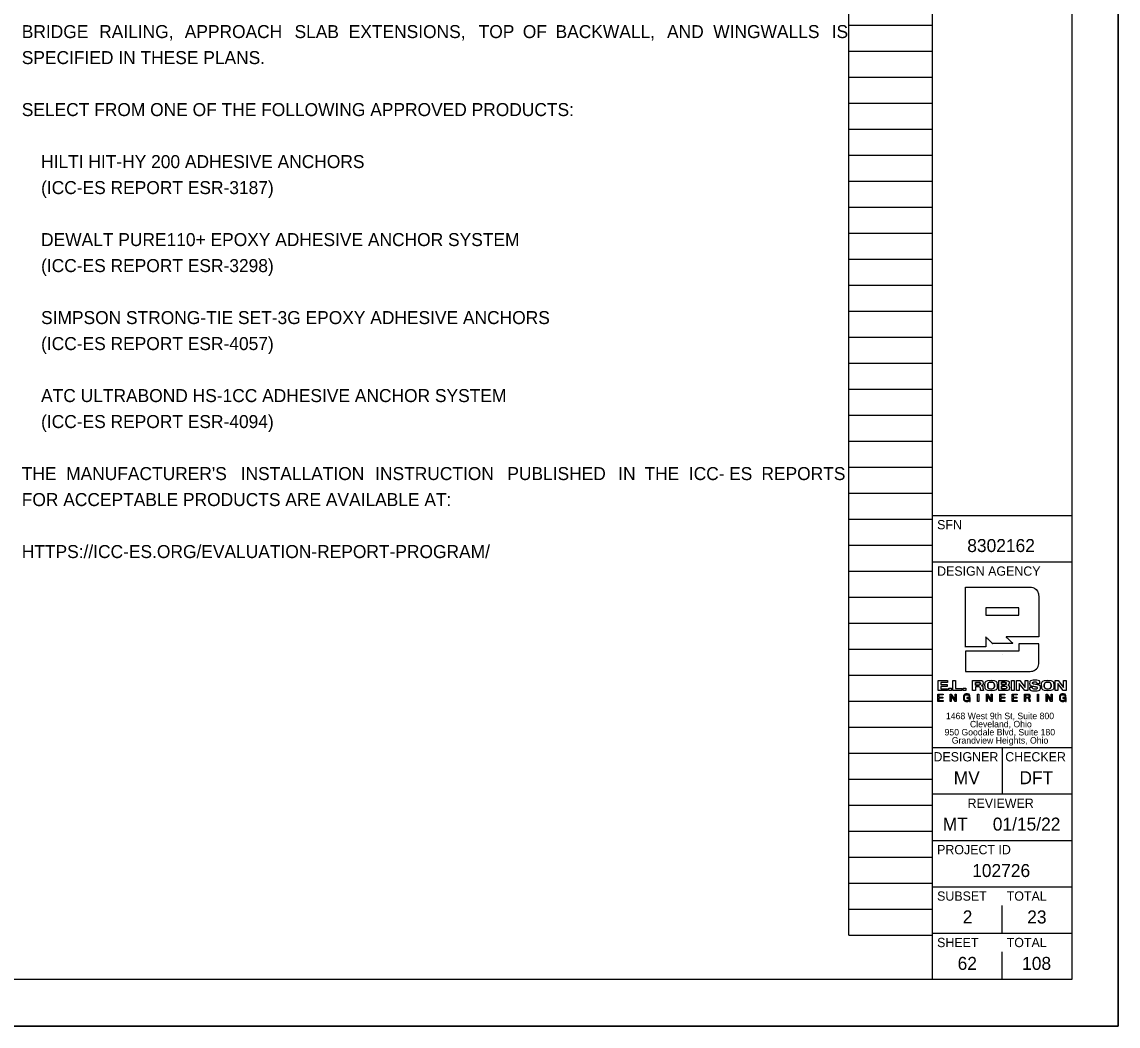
# Model space of a CAD drawing. Extents: x 0 to 34, y 0 to 22.
# Drawn here: x 22.19 to 34, y 0 to 10.81 of the extents above; entities that cross this region are included whole.
import ezdxf

# ---------------------------------------------------------------- set-up
doc = ezdxf.new("R2010")
doc.units = 0
for name, color, linetype in [('SC_Scratch1', 7, 'Continuous'), ('SH_Border', 7, 'Continuous'), ('SH_Cut_Line', 7, 'Continuous'), ('SH_Data', 7, 'Continuous'), ('SH_Text', 7, 'Continuous')]:
    doc.layers.add(name, color=color, linetype=linetype)

msp = doc.modelspace()

# ---------------------------------------------------------------- linework, layer by layer
at = {"layer": 'SC_Scratch1'}
for p, q in [((31.1, 0.98), (31.1, 21.14)), ((32, 0.98), (32, 21.14)), ((31.1, 10.78), (32, 10.78)), ((31.1, 10.5), (32, 10.5)), ((31.1, 10.22), (32, 10.22)), ((31.1, 9.94), (32, 9.94)), ((31.1, 9.66), (32, 9.66)), ((31.1, 9.38), (32, 9.38)), ((31.1, 9.1), (32, 9.1)), ((31.1, 8.82), (32, 8.82)), ((31.1, 8.54), (32, 8.54)), ((31.1, 8.26), (32, 8.26)), ((31.1, 7.98), (32, 7.98)), ((31.1, 7.7), (32, 7.7)), ((31.1, 7.42), (32, 7.42)), ((31.1, 7.14), (32, 7.14)), ((31.1, 6.86), (32, 6.86)), ((31.1, 6.58), (32, 6.58)), ((31.1, 6.3), (32, 6.3)), ((31.1, 6.02), (32, 6.02)), ((31.1, 5.74), (32, 5.74)), ((31.1, 5.46), (32, 5.46)), ((31.1, 5.18), (32, 5.18)), ((31.1, 4.9), (32, 4.9)), ((31.1, 4.62), (32, 4.62)), ((31.1, 4.34), (32, 4.34)), ((31.1, 4.06), (32, 4.06)), ((31.1, 3.78), (32, 3.78)), ((31.1, 3.5), (32, 3.5)), ((31.1, 3.22), (32, 3.22)), ((31.1, 2.94), (32, 2.94)), ((31.1, 2.66), (32, 2.66)), ((31.1, 2.38), (32, 2.38)), ((31.1, 2.1), (32, 2.1)), ((31.1, 1.82), (32, 1.82)), ((31.1, 1.54), (32, 1.54)), ((31.1, 1.26), (32, 1.26)), ((31.1, 0.98), (32, 0.98))]:
    msp.add_line(p, q, dxfattribs=at)
msp.add_lwpolyline([(0, 22), (34, 22), (34, 0), (0, 0)], close=True, dxfattribs=at)
at = {"layer": 'SH_Border'}
for p, q in [((32, 0.5), (32, 21.5)), ((32, 5.5), (33.5, 5.5)), ((32, 5), (33.5, 5)), ((32, 3), (33.5, 3)), ((32.75, 3), (32.75, 2.5)), ((32, 2.5), (33.5, 2.5)), ((32, 2), (33.5, 2)), ((32, 1.5), (33.5, 1.5)), ((32, 1), (33.5, 1))]:
    msp.add_line(p, q, dxfattribs=at)
msp.add_lwpolyline([(1.5, 21.5), (33.5, 21.5), (33.5, 0.5), (1.5, 0.5)], close=True, dxfattribs=at)
at = {"layer": 'SH_Cut_Line'}
msp.add_lwpolyline([(0, 0), (34, 0), (34, 22), (0, 22)], close=True, dxfattribs=at)
at = {"layer": 'SH_Data'}
for p, q in [((32.929, 4.503), (32.574, 4.503)), ((32.574, 4.503), (32.574, 4.425)), ((32.929, 4.425), (32.929, 4.503)), ((32.574, 4.425), (32.929, 4.425)), ((32.75, 4), (32.75, 4)), ((32.463, 3.701), (32.463, 3.673)), ((32.743, 3.702), (32.743, 3.678)), ((32.743, 3.659), (32.743, 3.633)), ((33.001, 3.566), (33.001, 3.539)), ((33.001, 3.539), (33.023, 3.539)), ((32.75, 1), (32.75, 1.3)), ((32.75, 0.5), (32.75, 0.8)), ((32.375, 0.675), (32.375, 0.675))]:
    msp.add_line(p, q, dxfattribs=at)
for points in [[(32.06, 3.721), (32.161, 3.721), (32.161, 3.701), (32.089, 3.701), (32.089, 3.678), (32.158, 3.678), (32.158, 3.658), (32.089, 3.658), (32.089, 3.633), (32.162, 3.633), (32.162, 3.613), (32.06, 3.613), (32.06, 3.721)], [(32.22, 3.721), (32.249, 3.721), (32.249, 3.634), (32.316, 3.634), (32.316, 3.613), (32.22, 3.613), (32.22, 3.721)], [(32.851, 3.721), (32.881, 3.721), (32.881, 3.613), (32.851, 3.613), (32.851, 3.721)], [(32.999, 3.721), (33.027, 3.721), (33.027, 3.613), (32.995, 3.613), (32.936, 3.689), (32.936, 3.689), (32.936, 3.613), (32.907, 3.613), (32.907, 3.721), (32.941, 3.721), (32.999, 3.646), (32.999, 3.646), (32.999, 3.721)], [(33.413, 3.721), (33.442, 3.721), (33.442, 3.613), (33.41, 3.613), (33.35, 3.689), (33.35, 3.689), (33.35, 3.613), (33.321, 3.613), (33.321, 3.721), (33.356, 3.721), (33.413, 3.646), (33.413, 3.646), (33.413, 3.721)], [(32.059, 3.575), (32.114, 3.575), (32.114, 3.566), (32.07, 3.566), (32.07, 3.541), (32.111, 3.541), (32.111, 3.532), (32.07, 3.532), (32.07, 3.505), (32.114, 3.505), (32.114, 3.496), (32.059, 3.496), (32.059, 3.575)], [(32.175, 3.639), (32.205, 3.639), (32.205, 3.613), (32.175, 3.613), (32.175, 3.639)], [(32.191, 3.575), (32.203, 3.575), (32.244, 3.511), (32.244, 3.511), (32.244, 3.575), (32.254, 3.575), (32.254, 3.496), (32.243, 3.496), (32.202, 3.559), (32.201, 3.559), (32.201, 3.496), (32.191, 3.496), (32.191, 3.575)], [(32.331, 3.639), (32.361, 3.639), (32.361, 3.613), (32.331, 3.613), (32.331, 3.639)], [(32.487, 3.575), (32.498, 3.575), (32.498, 3.496), (32.487, 3.496), (32.487, 3.575)], [(32.581, 3.575), (32.592, 3.575), (32.633, 3.511), (32.633, 3.511), (32.633, 3.575), (32.643, 3.575), (32.643, 3.496), (32.632, 3.496), (32.591, 3.559), (32.591, 3.559), (32.591, 3.496), (32.581, 3.496), (32.581, 3.575)], [(32.726, 3.575), (32.781, 3.575), (32.781, 3.566), (32.737, 3.566), (32.737, 3.541), (32.778, 3.541), (32.778, 3.532), (32.737, 3.532), (32.737, 3.505), (32.781, 3.505), (32.781, 3.496), (32.726, 3.496), (32.726, 3.575)], [(32.859, 3.575), (32.913, 3.575), (32.913, 3.566), (32.869, 3.566), (32.869, 3.541), (32.91, 3.541), (32.91, 3.532), (32.869, 3.532), (32.869, 3.505), (32.913, 3.505), (32.913, 3.496), (32.859, 3.496), (32.859, 3.575)], [(33.133, 3.575), (33.143, 3.575), (33.143, 3.496), (33.133, 3.496), (33.133, 3.575)], [(33.226, 3.575), (33.237, 3.575), (33.279, 3.511), (33.279, 3.511), (33.279, 3.575), (33.289, 3.575), (33.289, 3.496), (33.277, 3.496), (33.236, 3.559), (33.236, 3.559), (33.236, 3.496), (33.226, 3.496), (33.226, 3.575)]]:
    msp.add_lwpolyline(points, dxfattribs=at)
for points, degree in [([(32.356, 4.083), (32.356, 4.086), (32.356, 4.724), (32.356, 4.727)], 2), ([(32.356, 4.727), (32.36, 4.727), (33.03, 4.727), (33.034, 4.727), (33.096, 4.727), (33.147, 4.677), (33.147, 4.614)], 3), ([(33.147, 4.614), (33.147, 4.612), (33.147, 4.194), (33.147, 4.192)], 2), ([(32.645, 4.121), (32.645, 4.121), (32.574, 4.191), (32.574, 4.192)], 2), ([(32.574, 4.192), (32.574, 4.191), (32.574, 4.083), (32.574, 4.083)], 2), ([(33.147, 4.192), (33.145, 4.192), (32.795, 4.192), (32.793, 4.192)], 2), ([(32.793, 4.192), (32.793, 4.191), (32.866, 4.121), (32.866, 4.121)], 2), ([(32.929, 4.115), (32.929, 4.115), (33.147, 4.115), (33.147, 4.115), (33.147, 4.115), (33.147, 3.933), (33.147, 3.933), (33.147, 3.87), (33.096, 3.82), (33.034, 3.82), (33.034, 3.82), (32.356, 3.82), (32.356, 3.82), (32.356, 3.82), (32.356, 4.037), (32.356, 4.037), (32.356, 4.037), (32.929, 4.037), (32.929, 4.037), (32.929, 4.037), (32.929, 4.115), (32.929, 4.115)], 3), ([(32.574, 4.083), (32.573, 4.083), (32.357, 4.083), (32.356, 4.083)], 2), ([(32.866, 4.121), (32.865, 4.121), (32.646, 4.121), (32.645, 4.121)], 2), ([(32.433, 3.613), (32.433, 3.613), (32.433, 3.721), (32.433, 3.721)], 2), ([(32.433, 3.721), (32.433, 3.721), (32.512, 3.721), (32.512, 3.721), (32.542, 3.721), (32.545, 3.703), (32.546, 3.692)], 3), ([(32.463, 3.673), (32.463, 3.673), (32.502, 3.673), (32.502, 3.673), (32.508, 3.673), (32.516, 3.677), (32.516, 3.687), (32.516, 3.698), (32.507, 3.701), (32.5, 3.701), (32.5, 3.701), (32.463, 3.701), (32.463, 3.701), (32.463, 3.701), (32.463, 3.673), (32.463, 3.673)], 3), ([(32.463, 3.673), (32.476, 3.673), (32.489, 3.673), (32.508, 3.673), (32.516, 3.677), (32.516, 3.698), (32.507, 3.701), (32.488, 3.701), (32.475, 3.701), (32.463, 3.701)], 3), ([(32.546, 3.692), (32.544, 3.679), (32.542, 3.67), (32.53, 3.666)], 2), ([(32.53, 3.666), (32.53, 3.666), (32.53, 3.665), (32.53, 3.665)], 2), ([(32.53, 3.665), (32.543, 3.663), (32.544, 3.647), (32.544, 3.636)], 2), ([(32.631, 3.61), (32.573, 3.61), (32.567, 3.645), (32.565, 3.667), (32.564, 3.69), (32.573, 3.724), (32.631, 3.724)], 3), ([(32.631, 3.63), (32.658, 3.63), (32.667, 3.65), (32.667, 3.667), (32.667, 3.684), (32.658, 3.704), (32.631, 3.704), (32.604, 3.704), (32.595, 3.684), (32.595, 3.667), (32.595, 3.65), (32.604, 3.63), (32.631, 3.63)], 3), ([(32.631, 3.704), (32.604, 3.704), (32.595, 3.684), (32.595, 3.667), (32.595, 3.65), (32.604, 3.63), (32.631, 3.63)], 3), ([(32.631, 3.724), (32.69, 3.724), (32.695, 3.689), (32.697, 3.667), (32.699, 3.644), (32.69, 3.61), (32.631, 3.61)], 3), ([(32.631, 3.63), (32.658, 3.63), (32.667, 3.65), (32.667, 3.667), (32.667, 3.684), (32.658, 3.704), (32.631, 3.704)], 3), ([(32.714, 3.613), (32.714, 3.613), (32.714, 3.721), (32.714, 3.721)], 2), ([(32.714, 3.721), (32.714, 3.721), (32.795, 3.721), (32.795, 3.721)], 2), ([(32.743, 3.678), (32.743, 3.678), (32.784, 3.678), (32.784, 3.678), (32.791, 3.678), (32.796, 3.682), (32.796, 3.69), (32.796, 3.697), (32.793, 3.702), (32.78, 3.702), (32.78, 3.702), (32.743, 3.702), (32.743, 3.702), (32.743, 3.702), (32.743, 3.678), (32.743, 3.678)], 3), ([(32.743, 3.678), (32.757, 3.678), (32.771, 3.678), (32.791, 3.681), (32.791, 3.683), (32.792, 3.697), (32.793, 3.702), (32.768, 3.702), (32.756, 3.702), (32.743, 3.702)], 3), ([(32.795, 3.721), (32.81, 3.718), (32.826, 3.714), (32.826, 3.694)], 2), ([(32.826, 3.694), (32.824, 3.686), (32.822, 3.675), (32.812, 3.672)], 2), ([(32.812, 3.672), (32.812, 3.672), (32.812, 3.672), (32.812, 3.672)], 2), ([(32.812, 3.672), (32.824, 3.67), (32.827, 3.656), (32.829, 3.645)], 2), ([(33.126, 3.69), (33.124, 3.704), (33.111, 3.706), (33.099, 3.706), (33.087, 3.706), (33.079, 3.7), (33.079, 3.693), (33.079, 3.687), (33.084, 3.684), (33.091, 3.683), (33.091, 3.683), (33.128, 3.677), (33.128, 3.677), (33.148, 3.673), (33.163, 3.666), (33.163, 3.646), (33.163, 3.626), (33.149, 3.61), (33.107, 3.61), (33.08, 3.61), (33.046, 3.613), (33.045, 3.647), (33.045, 3.647), (33.079, 3.647), (33.079, 3.647), (33.079, 3.632), (33.094, 3.629), (33.107, 3.629), (33.121, 3.629), (33.13, 3.634), (33.13, 3.643), (33.13, 3.651), (33.123, 3.654), (33.112, 3.655), (33.112, 3.655), (33.085, 3.66), (33.085, 3.66), (33.066, 3.662), (33.047, 3.668), (33.047, 3.69), (33.047, 3.715), (33.067, 3.724), (33.101, 3.724), (33.124, 3.724), (33.157, 3.721), (33.159, 3.69), (33.159, 3.69), (33.126, 3.69), (33.126, 3.69)], 3), ([(33.242, 3.61), (33.183, 3.61), (33.178, 3.645), (33.176, 3.667), (33.174, 3.69), (33.183, 3.724), (33.242, 3.724)], 3), ([(33.242, 3.63), (33.269, 3.63), (33.278, 3.65), (33.278, 3.667), (33.278, 3.684), (33.269, 3.704), (33.242, 3.704), (33.215, 3.704), (33.205, 3.684), (33.205, 3.667), (33.205, 3.65), (33.215, 3.63), (33.242, 3.63)], 3), ([(33.242, 3.704), (33.215, 3.704), (33.205, 3.684), (33.205, 3.667), (33.205, 3.65), (33.215, 3.63), (33.242, 3.63)], 3), ([(33.242, 3.724), (33.3, 3.724), (33.306, 3.689), (33.308, 3.667), (33.309, 3.644), (33.3, 3.61), (33.242, 3.61)], 3), ([(33.242, 3.63), (33.269, 3.63), (33.278, 3.65), (33.278, 3.667), (33.278, 3.684), (33.269, 3.704), (33.242, 3.704)], 3), ([(32.396, 3.506), (32.39, 3.498), (32.38, 3.494), (32.37, 3.494), (32.347, 3.494), (32.333, 3.514), (32.333, 3.534), (32.333, 3.557), (32.346, 3.577), (32.37, 3.577), (32.388, 3.577), (32.401, 3.569), (32.404, 3.551), (32.404, 3.551), (32.394, 3.551), (32.394, 3.551), (32.392, 3.562), (32.382, 3.568), (32.37, 3.568), (32.351, 3.568), (32.344, 3.551), (32.344, 3.534), (32.344, 3.518), (32.353, 3.503), (32.37, 3.503), (32.387, 3.503), (32.396, 3.515), (32.396, 3.529), (32.396, 3.529), (32.371, 3.529), (32.371, 3.529), (32.371, 3.529), (32.371, 3.538), (32.371, 3.538), (32.371, 3.538), (32.405, 3.538), (32.405, 3.538), (32.405, 3.538), (32.405, 3.496), (32.405, 3.496), (32.405, 3.496), (32.398, 3.496), (32.398, 3.496), (32.398, 3.496), (32.396, 3.506), (32.396, 3.506)], 3), ([(32.463, 3.613), (32.462, 3.613), (32.433, 3.613), (32.433, 3.613)], 2), ([(32.499, 3.653), (32.499, 3.653), (32.463, 3.653), (32.463, 3.653)], 2), ([(32.463, 3.653), (32.463, 3.652), (32.463, 3.613), (32.463, 3.613)], 2), ([(32.518, 3.613), (32.516, 3.618), (32.516, 3.622), (32.516, 3.634), (32.515, 3.649), (32.508, 3.65), (32.499, 3.653)], 3), ([(32.55, 3.613), (32.55, 3.613), (32.518, 3.613), (32.518, 3.613)], 2), ([(32.544, 3.636), (32.544, 3.631), (32.548, 3.619), (32.55, 3.613)], 2), ([(32.829, 3.645), (32.827, 3.632), (32.824, 3.613), (32.791, 3.613), (32.791, 3.613), (32.714, 3.613), (32.714, 3.613)], 3), ([(32.743, 3.633), (32.743, 3.633), (32.787, 3.633), (32.787, 3.633), (32.796, 3.633), (32.8, 3.639), (32.8, 3.646), (32.8, 3.655), (32.794, 3.659), (32.784, 3.659), (32.784, 3.659), (32.743, 3.659), (32.743, 3.659), (32.743, 3.659), (32.743, 3.633), (32.743, 3.633)], 3), ([(32.743, 3.633), (32.758, 3.633), (32.772, 3.633), (32.796, 3.633), (32.8, 3.639), (32.8, 3.655), (32.794, 3.659), (32.77, 3.659), (32.757, 3.659), (32.743, 3.659)], 3), ([(32.991, 3.575), (32.991, 3.575), (33.027, 3.575), (33.028, 3.575), (33.042, 3.575), (33.051, 3.567), (33.051, 3.554)], 3), ([(32.991, 3.496), (32.991, 3.497), (32.991, 3.574), (32.991, 3.575)], 2), ([(33.023, 3.539), (33.033, 3.539), (33.041, 3.541), (33.041, 3.552), (33.041, 3.56), (33.037, 3.566), (33.027, 3.566), (33.027, 3.566), (33.001, 3.566), (33.001, 3.566), (33.001, 3.566), (33.001, 3.539), (33.001, 3.539), (33.001, 3.539), (33.023, 3.539), (33.023, 3.539)], 3), ([(33.023, 3.539), (33.033, 3.539), (33.041, 3.541), (33.041, 3.56), (33.037, 3.566), (33.018, 3.566), (33.01, 3.566), (33.001, 3.566)], 3), ([(33.051, 3.554), (33.049, 3.545), (33.047, 3.537), (33.038, 3.534)], 2), ([(33.43, 3.506), (33.424, 3.498), (33.414, 3.494), (33.405, 3.494), (33.382, 3.494), (33.368, 3.514), (33.368, 3.534), (33.368, 3.557), (33.38, 3.577), (33.405, 3.577), (33.422, 3.577), (33.436, 3.569), (33.439, 3.551), (33.439, 3.551), (33.429, 3.551), (33.429, 3.551), (33.426, 3.562), (33.417, 3.568), (33.405, 3.568), (33.386, 3.568), (33.378, 3.551), (33.378, 3.534), (33.378, 3.518), (33.388, 3.503), (33.405, 3.503), (33.421, 3.503), (33.431, 3.515), (33.43, 3.529), (33.43, 3.529), (33.405, 3.529), (33.405, 3.529), (33.405, 3.529), (33.405, 3.538), (33.405, 3.538), (33.405, 3.538), (33.44, 3.538), (33.44, 3.538), (33.44, 3.538), (33.44, 3.496), (33.44, 3.496), (33.44, 3.496), (33.433, 3.496), (33.433, 3.496), (33.433, 3.496), (33.43, 3.506), (33.43, 3.506)], 3), ([(33.001, 3.496), (33.001, 3.496), (32.991, 3.496), (32.991, 3.496)], 2), ([(33.04, 3.516), (33.038, 3.523), (33.037, 3.53), (33.027, 3.53), (33.027, 3.53), (33.001, 3.53), (33.001, 3.53)], 3), ([(33.001, 3.53), (33.001, 3.53), (33.001, 3.496), (33.001, 3.496)], 2), ([(33.038, 3.534), (33.038, 3.534), (33.038, 3.534), (33.038, 3.534)], 2), ([(33.038, 3.534), (33.044, 3.529), (33.047, 3.525), (33.048, 3.518)], 2), ([(33.043, 3.496), (33.042, 3.5), (33.041, 3.508), (33.04, 3.516)], 2), ([(33.054, 3.496), (33.054, 3.496), (33.043, 3.496), (33.043, 3.496)], 2), ([(33.048, 3.518), (33.049, 3.51), (33.052, 3.502), (33.054, 3.496)], 2)]:
    msp.add_open_spline(points, degree=degree, dxfattribs=at)

# ---------------------------------------------------------------- texts
for s, height, p in [('SFN', 0.1, (32.05, 5.35)), ('8302162', 0.14, (32.375, 5.105)), ('DESIGN AGENCY', 0.1, (32.05, 4.85)), ('1468 West 9th St, Suite 800', 0.07, (32.145, 3.305)), ('950 Goodale Blvd, Suite 180', 0.07, (32.13, 3.13)), ('Cleveland, Ohio', 0.07, (32.404, 3.217)), ('Grandview Heights, Ohio', 0.07, (32.208, 3.042)), ('DESIGNER', 0.1, (32.011, 2.85)), ('CHECKER', 0.1, (32.784, 2.85)), ('MV', 0.14, (32.229, 2.605)), ('DFT', 0.14, (32.937, 2.605)), ('REVIEWER', 0.1, (32.378, 2.35)), ('MT', 0.14, (32.111, 2.105)), ('01/15/22', 0.14, (32.65, 2.105)), ('PROJECT ID', 0.1, (32.05, 1.85)), ('102726', 0.14, (32.428, 1.605)), ('SUBSET', 0.1, (32.05, 1.35)), ('TOTAL', 0.1, (32.8, 1.35)), ('2', 0.14, (32.326, 1.105)), ('23', 0.14, (33.021, 1.105)), ('SHEET', 0.1, (32.05, 0.85)), ('TOTAL', 0.1, (32.8, 0.85)), ('62', 0.14, (32.271, 0.605)), ('108', 0.14, (32.966, 0.605))]:
    msp.add_text(s, height=height, dxfattribs=at).set_placement(p)
at = {"layer": 'SH_Text'}
for s, p in [('BRIDGE ', (22.187, 10.64)), ('RAILING, ', (23.021, 10.64)), ('APPROACH ', (23.943, 10.64)), ('SLAB ', (25.126, 10.64)), ('EXTENSIONS, ', (25.71, 10.64)), ('TOP ', (27.11, 10.64)), ('OF ', (27.586, 10.64)), ('BACKWALL, ', (27.939, 10.64)), ('AND ', (29.14, 10.64)), ('WINGWALLS ', (29.638, 10.64)), ('IS ', (30.914, 10.64)), ('SPECIFIED IN THESE PLANS.', (22.187, 10.36)), ('SELECT FROM ONE OF THE FOLLOWING APPROVED PRODUCTS:   ', (22.187, 9.8)), ('    HILTI HIT-HY 200 ADHESIVE ANCHORS ', (22.187, 9.24)), ('    (ICC-ES REPORT ESR-3187) ', (22.187, 8.96)), ('    DEWALT PURE110+ EPOXY ADHESIVE ANCHOR SYSTEM  ', (22.187, 8.4)), ('    (ICC-ES REPORT ESR-3298) ', (22.187, 8.12)), ('    SIMPSON STRONG-TIE SET-3G EPOXY ADHESIVE ANCHORS   ', (22.187, 7.56)), ('    (ICC-ES REPORT ESR-4057) ', (22.187, 7.28)), ('    ATC ULTRABOND HS-1CC ADHESIVE ANCHOR SYSTEM   ', (22.187, 6.72)), ('    (ICC-ES REPORT ESR-4094) ', (22.187, 6.44)), ('THE ', (22.187, 5.88)), ("MANUFACTURER'S ", (22.665, 5.88)), ('INSTALLATION ', (24.546, 5.88)), ('INSTRUCTION ', (25.995, 5.88)), ('PUBLISHED ', (27.419, 5.88)), ('IN ', (28.614, 5.88)), ('THE ', (28.897, 5.88)), ('ICC-', (29.375, 5.88)), ('ES ', (29.809, 5.88)), ('REPORTS ', (30.157, 5.88)), ('FOR ACCEPTABLE PRODUCTS ARE AVAILABLE AT: ', (22.187, 5.6)), ('HTTPS://ICC-ES.ORG/EVALUATION-REPORT-PROGRAM/', (22.187, 5.04))]:
    msp.add_text(s, height=0.14, dxfattribs=at).set_placement(p)

doc.saveas('drawing.dxf')
